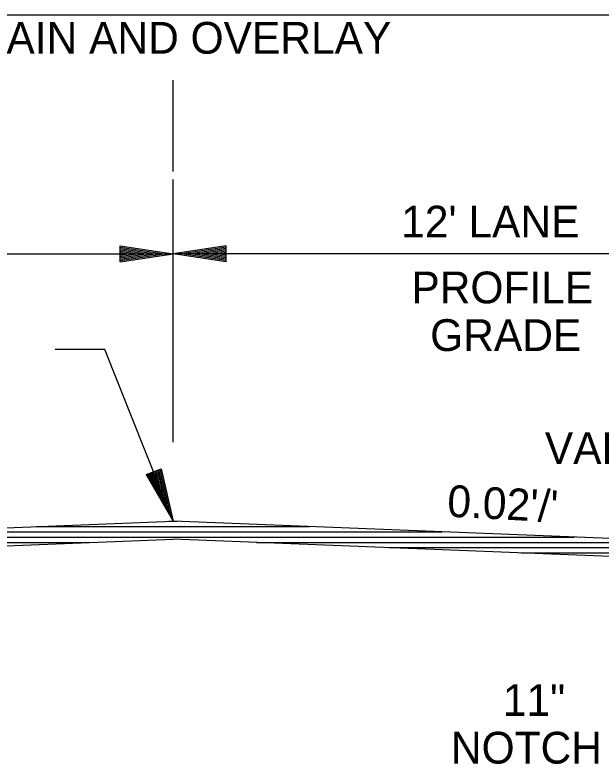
# Model space of a CAD drawing. Extents: x 1955768 to 1955917, y 566446 to 566546.
# Drawn here: x 1955836.69 to 1955847.75, y 566515.56 to 566529.71 of the extents above; entities that cross this region are included whole.
import ezdxf

# ---------------------------------------------------------------- set-up
doc = ezdxf.new("R2010")
doc.units = 0
doc.layers.add('R_Border', color=7, linetype='Continuous')
doc.layers.add('R_Grid', color=7, linetype='Continuous')

msp = doc.modelspace()

# ---------------------------------------------------------------- linework, layer by layer
at = {"layer": 'R_Border'}
for p, q in [((1955827.673, 566519.668), (1955839.673, 566520.148)), ((1955839.595, 566520.145), (1955839.75, 566520.145)), ((1955851.673, 566519.668), (1955839.673, 566520.148)), ((1955837.095, 566520.045), (1955842.25, 566520.045)), ((1955834.595, 566519.945), (1955844.75, 566519.945)), ((1955827.587, 566519.325), (1955839.673, 566519.808)), ((1955829.595, 566519.745), (1955838.097, 566519.745)), ((1955832.095, 566519.845), (1955847.25, 566519.845)), ((1955851.759, 566519.325), (1955839.673, 566519.808)), ((1955841.248, 566519.745), (1955849.75, 566519.745)), ((1955843.748, 566519.645), (1955852.265, 566519.645)), ((1955846.248, 566519.545), (1955854.675, 566519.545))]:
    msp.add_line(p, q, dxfattribs=at)
at = {"layer": 'R_Grid'}
for p, q in [((1955827.673, 566529.708), (1955851.672, 566529.708)), ((1955839.673, 566526.749), (1955839.673, 566528.478)), ((1955839.673, 566521.637), (1955839.673, 566526.599)), ((1955838.673, 566525.345), (1955839.673, 566525.195)), ((1955838.673, 566525.045), (1955838.673, 566525.345)), ((1955838.673, 566525.32), (1955839.506, 566525.195)), ((1955838.673, 566525.295), (1955839.334, 566525.195)), ((1955838.673, 566525.27), (1955839.167, 566525.195)), ((1955838.673, 566525.244), (1955838.998, 566525.195)), ((1955840.673, 566525.345), (1955839.673, 566525.195)), ((1955840.673, 566525.32), (1955839.84, 566525.195)), ((1955840.673, 566525.295), (1955840.012, 566525.195)), ((1955840.673, 566525.27), (1955840.178, 566525.195)), ((1955840.673, 566525.244), (1955840.348, 566525.195)), ((1955840.673, 566525.045), (1955840.673, 566525.345)), ((1955827.673, 566525.195), (1955839.673, 566525.195)), ((1955838.673, 566525.219), (1955838.831, 566525.195)), ((1955838.673, 566525.045), (1955839.673, 566525.195)), ((1955838.673, 566525.147), (1955838.998, 566525.195)), ((1955838.673, 566525.096), (1955839.334, 566525.195)), ((1955838.673, 566525.07), (1955839.506, 566525.195)), ((1955838.673, 566525.121), (1955839.167, 566525.195)), ((1955838.673, 566525.172), (1955838.831, 566525.195)), ((1955840.673, 566525.045), (1955839.673, 566525.195)), ((1955851.672, 566525.195), (1955839.673, 566525.195)), ((1955840.673, 566525.07), (1955839.84, 566525.195)), ((1955840.673, 566525.096), (1955840.012, 566525.195)), ((1955840.673, 566525.121), (1955840.178, 566525.195)), ((1955840.673, 566525.147), (1955840.348, 566525.195)), ((1955840.673, 566525.219), (1955840.515, 566525.195)), ((1955840.673, 566525.172), (1955840.515, 566525.195)), ((1955839.167, 566521.024), (1955839.446, 566521.134)), ((1955839.446, 566521.134), (1955839.673, 566520.148)), ((1955839.167, 566521.024), (1955839.673, 566520.148)), ((1955839.19, 566521.033), (1955839.612, 566520.304)), ((1955839.214, 566521.042), (1955839.549, 566520.464)), ((1955839.237, 566521.051), (1955839.488, 566520.619)), ((1955839.261, 566521.061), (1955839.425, 566520.776)), ((1955839.284, 566521.07), (1955839.364, 566520.932)), ((1955839.328, 566521.087), (1955839.364, 566520.932)), ((1955839.352, 566521.097), (1955839.425, 566520.776)), ((1955839.376, 566521.106), (1955839.488, 566520.619)), ((1955839.399, 566521.115), (1955839.549, 566520.464)), ((1955839.423, 566521.125), (1955839.612, 566520.304))]:
    msp.add_line(p, q, dxfattribs=at)
msp.add_lwpolyline([(1955839.673, 566520.148), (1955838.383, 566523.386), (1955837.449, 566523.386)], dxfattribs=at)

# ---------------------------------------------------------------- texts
at = {"layer": 'R_Border'}
for s, p in [('RETAIN AND OVERLAY', (1955834.922, 566528.976)), ("12' LANE", (1955843.981, 566525.505)), ('PROFILE', (1955844.173, 566524.26)), ('GRADE', (1955844.528, 566523.36)), ('VAR.', (1955846.693, 566521.225)), ('11" ', (1955845.9, 566516.466)), ('NOTCH', (1955844.919, 566515.566))]:
    msp.add_text(s, height=0.6, dxfattribs=at).set_placement(p)
msp.add_text("0.02'/'", height=0.6, rotation=356.9953, dxfattribs=at).set_placement((1955844.84, 566520.232))

doc.saveas('drawing.dxf')
